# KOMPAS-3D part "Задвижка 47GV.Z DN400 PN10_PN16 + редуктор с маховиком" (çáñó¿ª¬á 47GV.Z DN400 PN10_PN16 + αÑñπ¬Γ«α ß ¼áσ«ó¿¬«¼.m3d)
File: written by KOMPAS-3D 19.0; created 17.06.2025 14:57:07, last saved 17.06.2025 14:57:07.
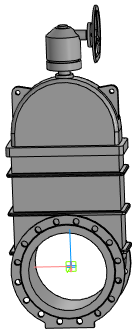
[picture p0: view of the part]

Document properties: Полное имя файла: Задвижка 47GV.Z DN400 PN10_PN16 + редуктор с маховиком.a3d

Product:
- Part/product: Задвижка 47GV.Z DN400 PN10_PN16 + редуктор с маховиком
    Масса: 782.432

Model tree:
1. Операция без истории:1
